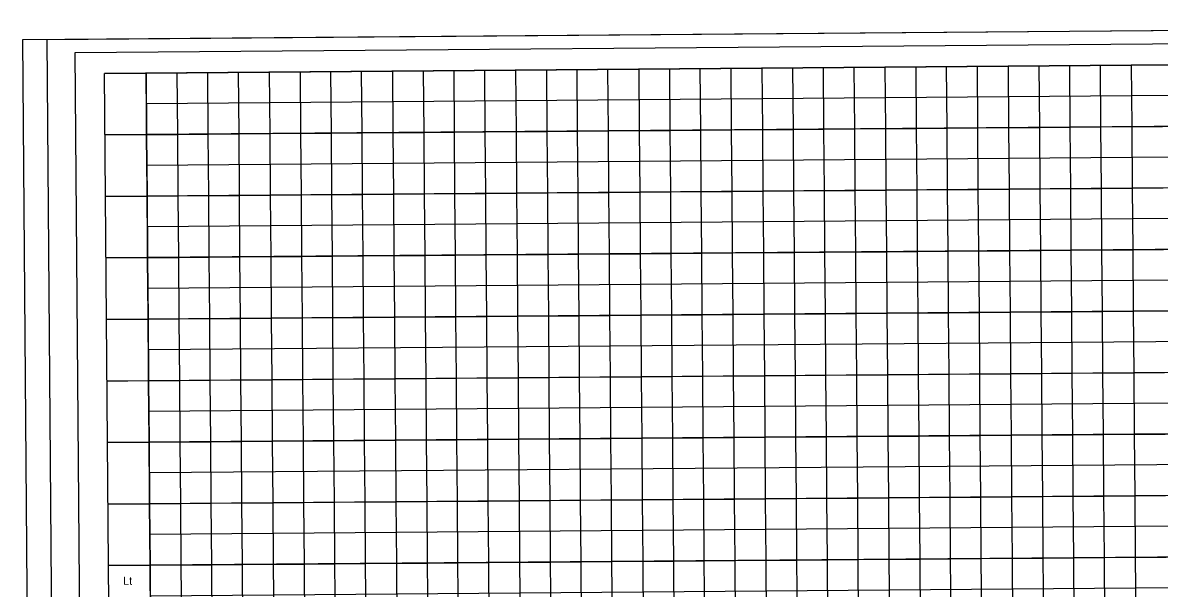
# Model space of a CAD drawing. Extents: x 11670159 to 11702568, y 9558247 to 9571922.
# Drawn here: x 11683828 to 11687520, y 9569018 to 9570857 of the extents above; entities that cross this region are included whole.
import ezdxf

# ---------------------------------------------------------------- set-up
doc = ezdxf.new("R2010")
doc.units = 0
for name, color, linetype in [('dsnNonPlotable', 7, 'Continuous'), ('DsnShtDBGLtRtTextUpper', 7, 'Continuous'), ('DsnShtMajorGrid12', 7, 'Continuous'), ('DsnShtMajorGrid13', 7, 'Continuous'), ('DsnShtMajorGrid14', 7, 'Continuous'), ('DsnShtMajorGrid15', 7, 'Continuous'), ('DsnShtMajorGrid16', 7, 'Continuous'), ('DsnShtMajorGrid17', 7, 'Continuous'), ('DsnShtMajorGrid18', 7, 'Continuous'), ('DsnShtMajorGrid19', 7, 'Continuous'), ('DsnShtMajorGrid20', 7, 'Continuous'), ('DsnShtMinorGrid12', 7, 'Continuous'), ('DsnShtMinorGrid13', 7, 'Continuous'), ('DsnShtMinorGrid14', 7, 'Continuous'), ('DsnShtMinorGrid15', 7, 'Continuous'), ('DsnShtMinorGrid16', 7, 'Continuous'), ('DsnShtMinorGrid17', 7, 'Continuous'), ('DsnShtMinorGrid18', 7, 'Continuous'), ('DsnShtMinorGrid19', 7, 'Continuous'), ('DsnShtMinorGrid20', 7, 'Continuous'), ('DsnShtOutsideBorder', 7, 'Continuous'), ('DsnShtPlotShape', 7, 'Continuous'), ('dsnShtPlotShapeBatchPrint', 7, 'Continuous'), ('hwyPlanSheetShape', 7, 'Continuous')]:
    doc.layers.add(name, color=color, linetype=linetype)

msp = doc.modelspace()

# ---------------------------------------------------------------- linework, layer by layer
at = {"layer": 'dsnNonPlotable'}
msp.add_lwpolyline([(11684229.4, 9570693), (11690229.2, 9570741.4), (11690261.8, 9566701.6), (11684262, 9566653.2)], close=True, dxfattribs=at)
at = {"layer": 'DsnShtMajorGrid12'}
for points in [[(11690377.1, 9569142.6), (11684107.3, 9569092), (11684242.3, 9569093.1), (11684243.9, 9568893.1)], [(11684443.9, 9568894.7), (11684442.3, 9569094.7), (11684642.3, 9569096.3), (11684643.9, 9568896.3)], [(11684843.9, 9568897.9), (11684842.3, 9569097.9), (11685042.3, 9569099.5), (11685043.9, 9568899.5)], [(11685243.9, 9568901.1), (11685242.3, 9569101.1), (11685442.3, 9569102.8), (11685443.9, 9568902.8)], [(11685643.9, 9568904.4), (11685642.2, 9569104.4), (11685842.2, 9569106), (11685843.9, 9568906)], [(11686043.8, 9568907.6), (11686042.2, 9569107.6), (11686242.2, 9569109.2), (11686243.8, 9568909.2)], [(11686443.8, 9568910.8), (11686442.2, 9569110.8), (11686642.2, 9569112.4), (11686643.8, 9568912.4)], [(11686843.8, 9568914.1), (11686842.2, 9569114), (11687042.2, 9569115.7), (11687043.8, 9568915.7)], [(11687243.8, 9568917.3), (11687242.2, 9569117.3), (11687442.2, 9569118.9), (11687443.8, 9568918.9)]]:
    msp.add_lwpolyline(points, dxfattribs=at)
at = {"layer": 'DsnShtMajorGrid13'}
for points in [[(11690375.5, 9569342.6), (11684105.7, 9569292), (11684240.7, 9569293.1), (11684242.3, 9569093.1), (11684442.3, 9569094.7), (11684440.7, 9569294.7), (11684640.7, 9569296.3), (11684642.3, 9569096.3), (11684842.3, 9569097.9), (11684840.7, 9569297.9), (11685040.7, 9569299.5), (11685042.3, 9569099.5), (11685242.3, 9569101.1), (11685240.6, 9569301.1), (11685440.6, 9569302.7), (11685442.3, 9569102.8), (11685642.2, 9569104.4), (11685640.6, 9569304.4), (11685840.6, 9569306), (11685842.2, 9569106), (11686042.2, 9569107.6), (11686040.6, 9569307.6), (11686240.6, 9569309.2), (11686242.2, 9569109.2), (11686442.2, 9569110.8), (11686440.6, 9569310.8), (11686640.6, 9569312.4), (11686642.2, 9569112.4), (11686842.2, 9569114), (11686840.6, 9569314), (11687040.6, 9569315.7), (11687042.2, 9569115.7), (11687242.2, 9569117.3), (11687240.6, 9569317.3), (11687440.6, 9569318.9), (11687442.2, 9569118.9), (11687642.2, 9569120.5)], [(11690377.1, 9569142.6), (11684107.3, 9569092)]]:
    msp.add_lwpolyline(points, dxfattribs=at)
at = {"layer": 'DsnShtMajorGrid14'}
for points in [[(11690373.9, 9569542.5), (11684104.1, 9569492), (11684239.1, 9569493.1), (11684240.7, 9569293.1), (11684440.7, 9569294.7), (11684439.1, 9569494.7), (11684639.1, 9569496.3), (11684640.7, 9569296.3), (11684840.7, 9569297.9), (11684839, 9569497.9), (11685039, 9569499.5), (11685040.7, 9569299.5), (11685240.6, 9569301.1), (11685239, 9569501.1), (11685439, 9569502.7), (11685440.6, 9569302.7), (11685640.6, 9569304.4), (11685639, 9569504.4), (11685839, 9569506), (11685840.6, 9569306), (11686040.6, 9569307.6), (11686039, 9569507.6), (11686239, 9569509.2), (11686240.6, 9569309.2), (11686440.6, 9569310.8), (11686439, 9569510.8), (11686639, 9569512.4), (11686640.6, 9569312.4), (11686840.6, 9569314), (11686839, 9569514), (11687039, 9569515.6), (11687040.6, 9569315.7), (11687240.6, 9569317.3), (11687239, 9569517.3), (11687439, 9569518.9), (11687440.6, 9569318.9), (11687640.6, 9569320.5)], [(11690375.5, 9569342.6), (11684105.7, 9569292)]]:
    msp.add_lwpolyline(points, dxfattribs=at)
at = {"layer": 'DsnShtMajorGrid15'}
for points in [[(11690372.3, 9569742.5), (11684102.5, 9569692), (11684237.5, 9569693.1), (11684239.1, 9569493.1), (11684439.1, 9569494.7), (11684437.4, 9569694.7), (11684637.4, 9569696.3), (11684639.1, 9569496.3), (11684839, 9569497.9), (11684837.4, 9569697.9), (11685037.4, 9569699.5), (11685039, 9569499.5), (11685239, 9569501.1), (11685237.4, 9569701.1), (11685437.4, 9569702.7), (11685439, 9569502.7), (11685639, 9569504.4), (11685637.4, 9569704.3), (11685837.4, 9569706), (11685839, 9569506), (11686039, 9569507.6), (11686037.4, 9569707.6), (11686237.4, 9569709.2), (11686239, 9569509.2), (11686439, 9569510.8), (11686437.4, 9569710.8), (11686637.4, 9569712.4), (11686639, 9569512.4), (11686839, 9569514), (11686837.4, 9569714), (11687037.4, 9569715.6), (11687039, 9569515.6), (11687239, 9569517.3), (11687237.4, 9569717.3), (11687437.3, 9569718.9), (11687439, 9569518.9), (11687639, 9569520.5)], [(11690373.9, 9569542.5), (11684104.1, 9569492)]]:
    msp.add_lwpolyline(points, dxfattribs=at)
at = {"layer": 'DsnShtMajorGrid16'}
for points in [[(11690370.6, 9569942.5), (11684100.8, 9569892), (11684235.8, 9569893), (11684237.5, 9569693.1), (11684437.4, 9569694.7), (11684435.8, 9569894.7), (11684635.8, 9569896.3), (11684637.4, 9569696.3), (11684837.4, 9569697.9), (11684835.8, 9569897.9), (11685035.8, 9569899.5), (11685037.4, 9569699.5), (11685237.4, 9569701.1), (11685235.8, 9569901.1), (11685435.8, 9569902.7), (11685437.4, 9569702.7), (11685637.4, 9569704.3), (11685635.8, 9569904.3), (11685835.8, 9569906), (11685837.4, 9569706), (11686037.4, 9569707.6), (11686035.8, 9569907.6), (11686235.8, 9569909.2), (11686237.4, 9569709.2), (11686437.4, 9569710.8), (11686435.8, 9569910.8), (11686635.8, 9569912.4), (11686637.4, 9569712.4), (11686837.4, 9569714), (11686835.8, 9569914), (11687035.7, 9569915.6), (11687037.4, 9569715.6), (11687237.4, 9569717.3), (11687235.7, 9569917.2), (11687435.7, 9569918.9), (11687437.3, 9569718.9), (11687637.3, 9569720.5)], [(11690372.3, 9569742.5), (11684102.5, 9569692)]]:
    msp.add_lwpolyline(points, dxfattribs=at)
at = {"layer": 'DsnShtMajorGrid17'}
for points in [[(11690369, 9570142.5), (11684099.2, 9570092), (11684234.2, 9570093), (11684235.8, 9569893), (11684435.8, 9569894.7), (11684434.2, 9570094.7), (11684634.2, 9570096.3), (11684635.8, 9569896.3), (11684835.8, 9569897.9), (11684834.2, 9570097.9), (11685034.2, 9570099.5), (11685035.8, 9569899.5), (11685235.8, 9569901.1), (11685234.2, 9570101.1), (11685434.2, 9570102.7), (11685435.8, 9569902.7), (11685635.8, 9569904.3), (11685634.2, 9570104.3), (11685834.2, 9570105.9), (11685835.8, 9569906), (11686035.8, 9569907.6), (11686034.2, 9570107.6), (11686234.2, 9570109.2), (11686235.8, 9569909.2), (11686435.8, 9569910.8), (11686434.2, 9570110.8), (11686634.1, 9570112.4), (11686635.8, 9569912.4), (11686835.8, 9569914), (11686834.1, 9570114), (11687034.1, 9570115.6), (11687035.7, 9569915.6), (11687235.7, 9569917.2), (11687234.1, 9570117.2), (11687434.1, 9570118.9), (11687435.7, 9569918.9), (11687635.7, 9569920.5)], [(11690370.6, 9569942.5), (11684100.8, 9569892)]]:
    msp.add_lwpolyline(points, dxfattribs=at)
at = {"layer": 'DsnShtMajorGrid18'}
for points in [[(11690367.4, 9570342.5), (11684097.6, 9570291.9), (11684232.6, 9570293), (11684234.2, 9570093), (11684434.2, 9570094.7), (11684432.6, 9570294.6), (11684632.6, 9570296.3), (11684634.2, 9570096.3), (11684834.2, 9570097.9), (11684832.6, 9570297.9), (11685032.6, 9570299.5), (11685034.2, 9570099.5), (11685234.2, 9570101.1), (11685232.6, 9570301.1), (11685432.6, 9570302.7), (11685434.2, 9570102.7), (11685634.2, 9570104.3), (11685632.6, 9570304.3), (11685832.6, 9570305.9), (11685834.2, 9570105.9), (11686034.2, 9570107.6), (11686032.6, 9570307.6), (11686232.5, 9570309.2), (11686234.2, 9570109.2), (11686434.2, 9570110.8), (11686432.5, 9570310.8), (11686632.5, 9570312.4), (11686634.1, 9570112.4), (11686834.1, 9570114), (11686832.5, 9570314), (11687032.5, 9570315.6), (11687034.1, 9570115.6), (11687234.1, 9570117.2), (11687232.5, 9570317.2), (11687432.5, 9570318.8), (11687434.1, 9570118.9), (11687634.1, 9570120.5)], [(11690369, 9570142.5), (11684099.2, 9570092)]]:
    msp.add_lwpolyline(points, dxfattribs=at)
at = {"layer": 'DsnShtMajorGrid19'}
for points in [[(11690365.8, 9570542.5), (11684096, 9570491.9), (11684231, 9570493), (11684232.6, 9570293), (11684432.6, 9570294.6), (11684431, 9570494.6), (11684631, 9570496.3), (11684632.6, 9570296.3), (11684832.6, 9570297.9), (11684831, 9570497.9), (11685031, 9570499.5), (11685032.6, 9570299.5), (11685232.6, 9570301.1), (11685231, 9570501.1), (11685431, 9570502.7), (11685432.6, 9570302.7), (11685632.6, 9570304.3), (11685631, 9570504.3), (11685830.9, 9570505.9), (11685832.6, 9570305.9), (11686032.6, 9570307.6), (11686030.9, 9570507.5), (11686230.9, 9570509.2), (11686232.5, 9570309.2), (11686432.5, 9570310.8), (11686430.9, 9570510.8), (11686630.9, 9570512.4), (11686632.5, 9570312.4), (11686832.5, 9570314), (11686830.9, 9570514), (11687030.9, 9570515.6), (11687032.5, 9570315.6), (11687232.5, 9570317.2), (11687230.9, 9570517.2), (11687430.9, 9570518.8), (11687432.5, 9570318.8), (11687632.5, 9570320.5)], [(11690367.4, 9570342.5), (11684097.6, 9570291.9)]]:
    msp.add_lwpolyline(points, dxfattribs=at)
at = {"layer": 'DsnShtMajorGrid20'}
for points in [[(11690364.2, 9570742.5), (11684094.4, 9570691.9), (11684229.4, 9570693), (11684231, 9570493), (11684431, 9570494.6), (11684429.4, 9570694.6), (11684629.4, 9570696.2), (11684631, 9570496.3), (11684831, 9570497.9), (11684829.4, 9570697.9), (11685029.4, 9570699.5), (11685031, 9570499.5), (11685231, 9570501.1), (11685229.4, 9570701.1), (11685429.3, 9570702.7), (11685431, 9570502.7), (11685631, 9570504.3), (11685629.3, 9570704.3), (11685829.3, 9570705.9), (11685830.9, 9570505.9), (11686030.9, 9570507.5), (11686029.3, 9570707.5), (11686229.3, 9570709.2), (11686230.9, 9570509.2), (11686430.9, 9570510.8), (11686429.3, 9570710.8), (11686629.3, 9570712.4), (11686630.9, 9570512.4), (11686830.9, 9570514), (11686829.3, 9570714), (11687029.3, 9570715.6), (11687030.9, 9570515.6), (11687230.9, 9570517.2), (11687229.3, 9570717.2), (11687429.3, 9570718.8), (11687430.9, 9570518.8), (11687630.9, 9570520.5)], [(11690365.8, 9570542.5), (11684096, 9570491.9)]]:
    msp.add_lwpolyline(points, dxfattribs=at)
at = {"layer": 'DsnShtMinorGrid12'}
for points in [[(11690242.9, 9569041.5), (11684243.1, 9568993.1), (11684242.3, 9569093.1), (11684342.3, 9569093.9), (11684343.9, 9568893.9)], [(11684543.9, 9568895.5), (11684542.3, 9569095.5), (11684742.3, 9569097.1), (11684743.9, 9568897.1)], [(11684943.9, 9568898.7), (11684942.3, 9569098.7), (11685142.3, 9569100.3), (11685143.9, 9568900.3)], [(11685343.9, 9568902), (11685342.3, 9569101.9), (11685542.2, 9569103.6), (11685543.9, 9568903.6)], [(11685743.9, 9568905.2), (11685742.2, 9569105.2), (11685942.2, 9569106.8), (11685943.8, 9568906.8)], [(11686143.8, 9568908.4), (11686142.2, 9569108.4), (11686342.2, 9569110), (11686343.8, 9568910)], [(11686543.8, 9568911.6), (11686542.2, 9569111.6), (11686742.2, 9569113.2), (11686743.8, 9568913.2)], [(11686943.8, 9568914.9), (11686942.2, 9569114.9), (11687142.2, 9569116.5), (11687143.8, 9568916.5)], [(11687343.8, 9568918.1), (11687342.2, 9569118.1), (11687542.2, 9569119.7)]]:
    msp.add_lwpolyline(points, dxfattribs=at)
at = {"layer": 'DsnShtMinorGrid13'}
msp.add_lwpolyline([(11690241.3, 9569241.5), (11684241.5, 9569193.1), (11684240.7, 9569293.1), (11684340.7, 9569293.9), (11684342.3, 9569093.9), (11684542.3, 9569095.5), (11684540.7, 9569295.5), (11684740.7, 9569297.1), (11684742.3, 9569097.1), (11684942.3, 9569098.7), (11684940.7, 9569298.7), (11685140.6, 9569300.3), (11685142.3, 9569100.3), (11685342.3, 9569101.9), (11685340.6, 9569301.9), (11685540.6, 9569303.6), (11685542.2, 9569103.6), (11685742.2, 9569105.2), (11685740.6, 9569305.2), (11685940.6, 9569306.8), (11685942.2, 9569106.8), (11686142.2, 9569108.4), (11686140.6, 9569308.4), (11686340.6, 9569310), (11686342.2, 9569110), (11686542.2, 9569111.6), (11686540.6, 9569311.6), (11686740.6, 9569313.2), (11686742.2, 9569113.2), (11686942.2, 9569114.9), (11686940.6, 9569314.8), (11687140.6, 9569316.5), (11687142.2, 9569116.5), (11687342.2, 9569118.1), (11687340.6, 9569318.1), (11687540.6, 9569319.7)], dxfattribs=at)
at = {"layer": 'DsnShtMinorGrid14'}
msp.add_lwpolyline([(11690239.7, 9569441.5), (11684239.9, 9569393.1), (11684239.1, 9569493.1), (11684339.1, 9569493.9), (11684340.7, 9569293.9), (11684540.7, 9569295.5), (11684539.1, 9569495.5), (11684739, 9569497.1), (11684740.7, 9569297.1), (11684940.7, 9569298.7), (11684939, 9569498.7), (11685139, 9569500.3), (11685140.6, 9569300.3), (11685340.6, 9569301.9), (11685339, 9569501.9), (11685539, 9569503.5), (11685540.6, 9569303.6), (11685740.6, 9569305.2), (11685739, 9569505.2), (11685939, 9569506.8), (11685940.6, 9569306.8), (11686140.6, 9569308.4), (11686139, 9569508.4), (11686339, 9569510), (11686340.6, 9569310), (11686540.6, 9569311.6), (11686539, 9569511.6), (11686739, 9569513.2), (11686740.6, 9569313.2), (11686940.6, 9569314.8), (11686939, 9569514.8), (11687139, 9569516.5), (11687140.6, 9569316.5), (11687340.6, 9569318.1), (11687339, 9569518.1), (11687539, 9569519.7)], dxfattribs=at)
at = {"layer": 'DsnShtMinorGrid15'}
msp.add_lwpolyline([(11690238.1, 9569641.5), (11684238.3, 9569593.1), (11684237.5, 9569693.1), (11684337.4, 9569693.9), (11684339.1, 9569493.9), (11684539.1, 9569495.5), (11684537.4, 9569695.5), (11684737.4, 9569697.1), (11684739, 9569497.1), (11684939, 9569498.7), (11684937.4, 9569698.7), (11685137.4, 9569700.3), (11685139, 9569500.3), (11685339, 9569501.9), (11685337.4, 9569701.9), (11685537.4, 9569703.5), (11685539, 9569503.5), (11685739, 9569505.2), (11685737.4, 9569705.2), (11685937.4, 9569706.8), (11685939, 9569506.8), (11686139, 9569508.4), (11686137.4, 9569708.4), (11686337.4, 9569710), (11686339, 9569510), (11686539, 9569511.6), (11686537.4, 9569711.6), (11686737.4, 9569713.2), (11686739, 9569513.2), (11686939, 9569514.8), (11686937.4, 9569714.8), (11687137.4, 9569716.4), (11687139, 9569516.5), (11687339, 9569518.1), (11687337.4, 9569718.1), (11687537.3, 9569719.7)], dxfattribs=at)
at = {"layer": 'DsnShtMinorGrid16'}
msp.add_lwpolyline([(11690236.5, 9569841.4), (11684236.6, 9569793.1), (11684235.8, 9569893), (11684335.8, 9569893.9), (11684337.4, 9569693.9), (11684537.4, 9569695.5), (11684535.8, 9569895.5), (11684735.8, 9569897.1), (11684737.4, 9569697.1), (11684937.4, 9569698.7), (11684935.8, 9569898.7), (11685135.8, 9569900.3), (11685137.4, 9569700.3), (11685337.4, 9569701.9), (11685335.8, 9569901.9), (11685535.8, 9569903.5), (11685537.4, 9569703.5), (11685737.4, 9569705.2), (11685735.8, 9569905.1), (11685935.8, 9569906.8), (11685937.4, 9569706.8), (11686137.4, 9569708.4), (11686135.8, 9569908.4), (11686335.8, 9569910), (11686337.4, 9569710), (11686537.4, 9569711.6), (11686535.8, 9569911.6), (11686735.8, 9569913.2), (11686737.4, 9569713.2), (11686937.4, 9569714.8), (11686935.8, 9569914.8), (11687135.7, 9569916.4), (11687137.4, 9569716.4), (11687337.4, 9569718.1), (11687335.7, 9569918.1), (11687535.7, 9569919.7)], dxfattribs=at)
at = {"layer": 'DsnShtMinorGrid17'}
msp.add_lwpolyline([(11690234.8, 9570041.4), (11684235, 9569993), (11684234.2, 9570093), (11684334.2, 9570093.8), (11684335.8, 9569893.9), (11684535.8, 9569895.5), (11684534.2, 9570095.5), (11684734.2, 9570097.1), (11684735.8, 9569897.1), (11684935.8, 9569898.7), (11684934.2, 9570098.7), (11685134.2, 9570100.3), (11685135.8, 9569900.3), (11685335.8, 9569901.9), (11685334.2, 9570101.9), (11685534.2, 9570103.5), (11685535.8, 9569903.5), (11685735.8, 9569905.1), (11685734.2, 9570105.1), (11685934.2, 9570106.8), (11685935.8, 9569906.8), (11686135.8, 9569908.4), (11686134.2, 9570108.4), (11686334.2, 9570110), (11686335.8, 9569910), (11686535.8, 9569911.6), (11686534.2, 9570111.6), (11686734.1, 9570113.2), (11686735.8, 9569913.2), (11686935.8, 9569914.8), (11686934.1, 9570114.8), (11687134.1, 9570116.4), (11687135.7, 9569916.4), (11687335.7, 9569918.1), (11687334.1, 9570118), (11687534.1, 9570119.7)], dxfattribs=at)
at = {"layer": 'DsnShtMinorGrid18'}
msp.add_lwpolyline([(11690233.2, 9570241.4), (11684233.4, 9570193), (11684232.6, 9570293), (11684332.6, 9570293.8), (11684334.2, 9570093.8), (11684534.2, 9570095.5), (11684532.6, 9570295.5), (11684732.6, 9570297.1), (11684734.2, 9570097.1), (11684934.2, 9570098.7), (11684932.6, 9570298.7), (11685132.6, 9570300.3), (11685134.2, 9570100.3), (11685334.2, 9570101.9), (11685332.6, 9570301.9), (11685532.6, 9570303.5), (11685534.2, 9570103.5), (11685734.2, 9570105.1), (11685732.6, 9570305.1), (11685932.6, 9570306.7), (11685934.2, 9570106.8), (11686134.2, 9570108.4), (11686132.6, 9570308.4), (11686332.5, 9570310), (11686334.2, 9570110), (11686534.2, 9570111.6), (11686532.5, 9570311.6), (11686732.5, 9570313.2), (11686734.1, 9570113.2), (11686934.1, 9570114.8), (11686932.5, 9570314.8), (11687132.5, 9570316.4), (11687134.1, 9570116.4), (11687334.1, 9570118), (11687332.5, 9570318), (11687532.5, 9570319.7)], dxfattribs=at)
at = {"layer": 'DsnShtMinorGrid19'}
msp.add_lwpolyline([(11690231.6, 9570441.4), (11684231.8, 9570393), (11684231, 9570493), (11684331, 9570493.8), (11684332.6, 9570293.8), (11684532.6, 9570295.5), (11684531, 9570495.4), (11684731, 9570497.1), (11684732.6, 9570297.1), (11684932.6, 9570298.7), (11684931, 9570498.7), (11685131, 9570500.3), (11685132.6, 9570300.3), (11685332.6, 9570301.9), (11685331, 9570501.9), (11685531, 9570503.5), (11685532.6, 9570303.5), (11685732.6, 9570305.1), (11685731, 9570505.1), (11685930.9, 9570506.7), (11685932.6, 9570306.7), (11686132.6, 9570308.4), (11686130.9, 9570508.4), (11686330.9, 9570510), (11686332.5, 9570310), (11686532.5, 9570311.6), (11686530.9, 9570511.6), (11686730.9, 9570513.2), (11686732.5, 9570313.2), (11686932.5, 9570314.8), (11686930.9, 9570514.8), (11687130.9, 9570516.4), (11687132.5, 9570316.4), (11687332.5, 9570318), (11687330.9, 9570518), (11687530.9, 9570519.6)], dxfattribs=at)
at = {"layer": 'DsnShtMinorGrid20'}
msp.add_lwpolyline([(11690230, 9570641.4), (11684230.2, 9570593), (11684229.4, 9570693), (11684329.4, 9570693.8), (11684331, 9570493.8), (11684531, 9570495.4), (11684529.4, 9570695.4), (11684729.4, 9570697.1), (11684731, 9570497.1), (11684931, 9570498.7), (11684929.4, 9570698.7), (11685129.4, 9570700.3), (11685131, 9570500.3), (11685331, 9570501.9), (11685329.4, 9570701.9), (11685529.3, 9570703.5), (11685531, 9570503.5), (11685731, 9570505.1), (11685729.3, 9570705.1), (11685929.3, 9570706.7), (11685930.9, 9570506.7), (11686130.9, 9570508.4), (11686129.3, 9570708.3), (11686329.3, 9570710), (11686330.9, 9570510), (11686530.9, 9570511.6), (11686529.3, 9570711.6), (11686729.3, 9570713.2), (11686730.9, 9570513.2), (11686930.9, 9570514.8), (11686929.3, 9570714.8), (11687129.3, 9570716.4), (11687130.9, 9570516.4), (11687330.9, 9570518), (11687329.3, 9570718), (11687529.3, 9570719.6)], dxfattribs=at)
at = {"layer": 'DsnShtOutsideBorder'}
msp.add_lwpolyline([(11684094.4, 9570691.9), (11690364.2, 9570742.5), (11690397.4, 9566622.6), (11684127.6, 9566572.1)], close=True, dxfattribs=at)
at = {"layer": 'DsnShtPlotShape'}
msp.add_lwpolyline([(11683828.5, 9570801.8), (11690628.3, 9570856.6), (11690663.8, 9566456.8), (11683864, 9566401.9)], close=True, dxfattribs=at)
at = {"layer": 'dsnShtPlotShapeBatchPrint'}
msp.add_lwpolyline([(11683907.6, 9570802.4), (11690549.2, 9570856), (11690584.6, 9566469.3), (11683943, 9566415.7)], close=True, dxfattribs=at)
at = {"layer": 'hwyPlanSheetShape'}
msp.add_lwpolyline([(11683998.8, 9570760.1), (11690458.6, 9570812.2), (11690493, 9566554), (11684033.2, 9566501.9)], close=True, dxfattribs=at)

# ---------------------------------------------------------------- texts
at = {"layer": 'DsnShtDBGLtRtTextUpper'}
msp.add_text('Lt', height=26, rotation=0.4622, dxfattribs=at).set_placement((11684154.8, 9569029.4))

doc.saveas('drawing.dxf')
